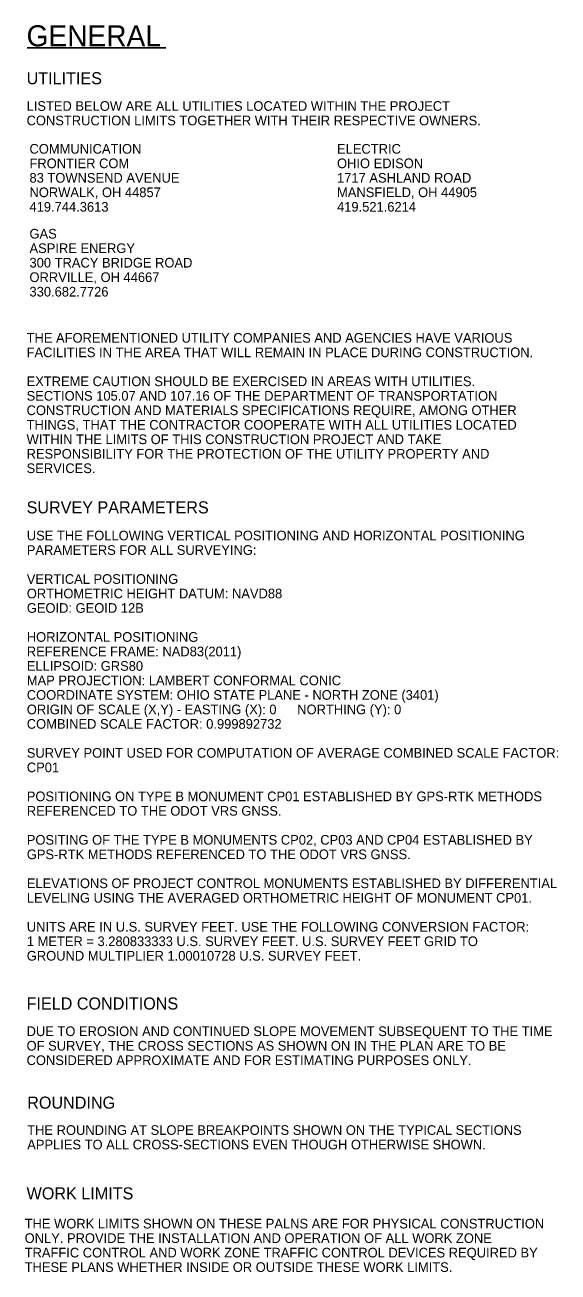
# Model space of a CAD drawing. Extents: x 0 to 43.5, y 0 to 44.1.
# Drawn here: x 3.08 to 10.8, y 26.04 to 44.11 of the extents above; entities that cross this region are included whole.
import ezdxf

# ---------------------------------------------------------------- set-up
doc = ezdxf.new("R2010")
doc.units = 0
doc.layers.add('Default', color=7, linetype='Continuous')
doc.layers.add('TX_P_1', color=7, linetype='Continuous')

msp = doc.modelspace()

# ---------------------------------------------------------------- linework, layer by layer
at = {"layer": 'Default'}
msp.add_line((3.107, 43.78), (5.12, 43.78), dxfattribs=at)

# ---------------------------------------------------------------- texts
at = {"layer": 'TX_P_1'}
for s, height, p in [('GENERAL', 0.3047, (3.1, 43.804)), ('UTILITIES', 0.175, (3.1, 43.254)), ('LISTED BELOW ARE ALL UTILITIES LOCATED WITHIN THE PROJECT ', 0.14, (3.1, 42.869)), ('CONSTRUCTION LIMITS TOGETHER WITH THEIR RESPECTIVE OWNERS.', 0.14, (3.1, 42.659)), ('COMMUNICATION', 0.14, (3.142, 42.248)), ('ELECTRIC', 0.14, (7.6, 42.248)), ('FRONTIER COM', 0.14, (3.142, 42.038)), ('OHIO EDISON', 0.14, (7.6, 42.038)), ('83 TOWNSEND AVENUE', 0.14, (3.142, 41.828)), ('1717 ASHLAND ROAD', 0.14, (7.6, 41.828)), ('NORWALK, OH 44857', 0.14, (3.142, 41.618)), ('MANSFIELD, OH 44905', 0.14, (7.6, 41.618)), ('419.744.3613', 0.14, (3.142, 41.408)), ('419.521.6214', 0.14, (7.6, 41.408)), ('GAS', 0.14, (3.142, 41.018)), ('ASPIRE ENERGY ', 0.14, (3.142, 40.808)), ('300 TRACY BRIDGE ROAD', 0.14, (3.142, 40.598)), ('ORRVILLE, OH 44667', 0.14, (3.142, 40.388)), ('330.682.7726', 0.14, (3.142, 40.178)), ('THE AFOREMENTIONED UTILITY COMPANIES AND AGENCIES HAVE VARIOUS ', 0.14, (3.1, 39.509)), ('FACILITIES IN THE AREA THAT WILL REMAIN IN PLACE DURING CONSTRUCTION.', 0.14, (3.1, 39.299)), ('EXTREME CAUTION SHOULD BE EXERCISED IN AREAS WITH UTILITIES.  ', 0.14, (3.1, 38.879)), ('SECTIONS 105.07 AND 107.16 OF THE DEPARTMENT OF TRANSPORTATION ', 0.14, (3.1, 38.669)), ('CONSTRUCTION AND MATERIALS SPECIFICATIONS REQUIRE, AMONG OTHER ', 0.14, (3.1, 38.459)), ('THINGS, THAT THE CONTRACTOR COOPERATE WITH ALL UTILITIES LOCATED ', 0.14, (3.1, 38.249)), ('WITHIN THE LIMITS OF THIS CONSTRUCTION PROJECT AND TAKE ', 0.14, (3.1, 38.039)), ('RESPONSIBILITY FOR THE PROTECTION OF THE UTILITY PROPERTY AND ', 0.14, (3.1, 37.829)), ('SERVICES.', 0.14, (3.1, 37.619)), ('SURVEY PARAMETERS', 0.175, (3.1, 37.035)), ('USE THE FOLLOWING VERTICAL POSITIONING AND HORIZONTAL POSITIONING ', 0.14, (3.103, 36.644)), ('PARAMETERS FOR ALL SURVEYING:', 0.14, (3.103, 36.434)), ('VERTICAL POSITIONING ', 0.14, (3.103, 36.014)), ('ORTHOMETRIC HEIGHT DATUM: NAVD88 ', 0.14, (3.103, 35.804)), ('GEOID: GEOID 12B', 0.14, (3.103, 35.594)), ('HORIZONTAL POSITIONING ', 0.14, (3.103, 35.174)), ('REFERENCE FRAME: NAD83(2011) ', 0.14, (3.103, 34.964)), ('ELLIPSOID: GRS80 ', 0.14, (3.103, 34.754)), ('MAP PROJECTION: LAMBERT CONFORMAL CONIC ', 0.14, (3.103, 34.544)), ('COORDINATE SYSTEM: OHIO STATE PLANE - NORTH ZONE (3401)', 0.14, (3.103, 34.334)), ('ORIGIN OF SCALE (X,Y) - EASTING (X): 0 ', 0.14, (3.103, 34.124)), ('NORTHING (Y): 0', 0.14, (7.023, 34.124)), ('COMBINED SCALE FACTOR: 0.999892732', 0.14, (3.103, 33.914)), ('SURVEY POINT USED FOR COMPUTATION OF AVERAGE COMBINED SCALE FACTOR:  ', 0.14, (3.103, 33.494)), ('CP01', 0.14, (3.103, 33.284)), ('POSITIONING ON TYPE B MONUMENT CP01 ESTABLISHED BY GPS-RTK METHODS ', 0.14, (3.103, 32.864)), ('REFERENCED TO THE ODOT VRS GNSS.', 0.14, (3.103, 32.654)), ('POSITING OF THE TYPE B MONUMENTS CP02, CP03 AND CP04 ESTABLISHED BY  ', 0.14, (3.103, 32.234)), ('GPS-RTK METHODS REFERENCED TO THE ODOT VRS GNSS.', 0.14, (3.103, 32.024)), ('ELEVATIONS OF PROJECT CONTROL MONUMENTS ESTABLISHED BY DIFFERENTIAL ', 0.14, (3.103, 31.604)), ('LEVELING USING THE AVERAGED ORTHOMETRIC HEIGHT OF MONUMENT CP01.', 0.14, (3.103, 31.394)), ('UNITS ARE IN U.S. SURVEY FEET. USE THE FOLLOWING CONVERSION FACTOR: ', 0.14, (3.103, 30.974)), ('1 METER = 3.280833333 U.S. SURVEY FEET. U.S. SURVEY FEET GRID TO  ', 0.14, (3.103, 30.764)), ('GROUND MULTIPLIER 1.00010728 U.S. SURVEY FEET.', 0.14, (3.103, 30.554)), ('FIELD CONDITIONS', 0.175, (3.1, 29.845)), ('DUE TO EROSION AND CONTINUED SLOPE MOVEMENT SUBSEQUENT TO THE TIME ', 0.14, (3.1, 29.46)), ('OF SURVEY, THE CROSS SECTIONS AS SHOWN ON IN THE PLAN ARE TO BE ', 0.14, (3.1, 29.25)), ('CONSIDERED APPROXIMATE AND FOR ESTIMATING PURPOSES ONLY.', 0.14, (3.1, 29.04)), ('ROUNDING', 0.175, (3.109, 28.408)), ('THE ROUNDING AT SLOPE BREAKPOINTS SHOWN ON THE TYPICAL SECTIONS ', 0.14, (3.109, 28.028)), ('APPLIES TO ALL CROSS-SECTIONS EVEN THOUGH OTHERWISE SHOWN.', 0.14, (3.109, 27.818)), ('WORK LIMITS', 0.175, (3.1, 27.093)), ('THE WORK LIMITS SHOWN ON THESE PALNS ARE FOR PHYSICAL CONSTRUCTION ', 0.14, (3.072, 26.672)), ('ONLY. PROVIDE THE INSTALLATION AND OPERATION OF ALL WORK ZONE ', 0.14, (3.072, 26.462)), ('TRAFFIC CONTROL AND WORK ZONE TRAFFIC CONTROL DEVICES REQUIRED BY ', 0.14, (3.072, 26.252)), ('THESE PLANS WHETHER INSIDE OR OUTSIDE THESE WORK LIMITS.', 0.14, (3.072, 26.042))]:
    msp.add_text(s, height=height, dxfattribs=at).set_placement(p)

doc.saveas('drawing.dxf')
